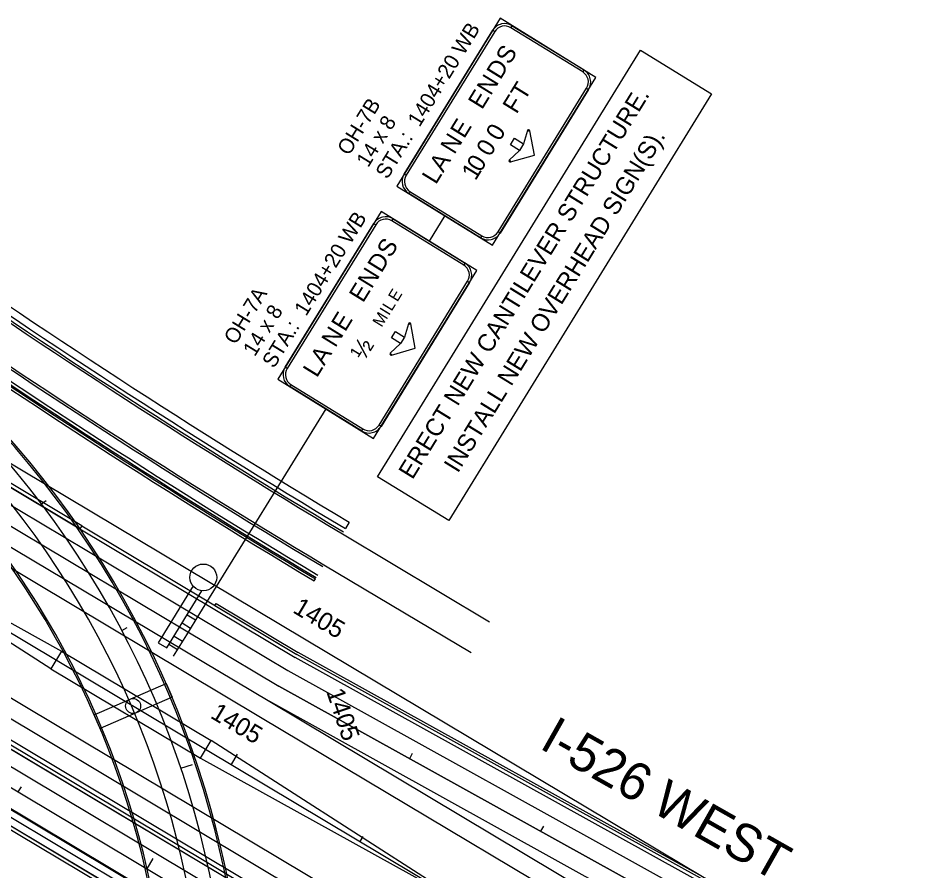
# Model space of a CAD drawing. Extents: x 2338610 to 2351914, y 366540 to 376484.
# Drawn here: x 2346817 to 2347427, y 369410 to 369978 of the extents above; entities that cross this region are included whole.
import ezdxf

# ---------------------------------------------------------------- set-up
doc = ezdxf.new("R2010")
doc.units = 0
for name, color, linetype in [('RD_HC_Cl', 7, 'Continuous'), ('RD_HC_CL_Rel', 7, 'Continuous'), ('RD_PD_Bridge', 7, 'Continuous'), ('RD_PD_Final_LnLine', 7, 'Continuous'), ('RD_PD_Final_TrvlWay', 7, 'Continuous'), ('RD_PD_FOC', 7, 'Continuous'), ('RD_PD_MedBWall', 7, 'Continuous'), ('RD_PD_NOISE-WALL-GM', 7, 'Continuous'), ('RD_PD_PaveShd', 7, 'Continuous'), ('RD_PD_SW', 7, 'Continuous'), ('TR PM UNASSIGNED 3', 7, 'Continuous'), ('TR SN EXTRUDED PANEL SIGNS- MOUNTED OVERHEAD', 7, 'Continuous'), ('TR SN UNASSIGNED 4', 7, 'Continuous'), ('TR SN UNASSIGNED 7', 7, 'Continuous')]:
    doc.layers.add(name, color=color, linetype=linetype)

msp = doc.modelspace()

# ---------------------------------------------------------------- linework, layer by layer
at = {"layer": 'RD_HC_Cl'}
for p, q in [((2346281.57, 369885.43), (2351112.4, 367003.22)), ((2346606.48, 369804.53), (2348463.13, 368696.8)), ((2346606.48, 369804.53), (2348463.13, 368696.8)), ((2346606.48, 369804.53), (2348463.13, 368696.8)), ((2346606.48, 369804.53), (2348463.13, 368696.8))]:
    msp.add_line(p, q, dxfattribs=at)
msp.add_arc((2346341.62, 369282.71), 616, 339.59346, 61.72492, dxfattribs=at)
at = {"layer": 'RD_HC_CL_Rel'}
for p, q in [((2346236.27, 369809.5), (2347935.64, 368795.61)), ((2346990.8, 369533.51), (2347672.36, 369155.93))]:
    msp.add_line(p, q, dxfattribs=at)
at = {"layer": 'RD_PD_Bridge'}
for p, q in [((2346858.25, 369638.21), (2346664.27, 369753.94)), ((2346859.45, 369640.21), (2346665.47, 369755.95)), ((2346859.45, 369640.21), (2346858.25, 369638.21)), ((2346845.89, 369556.79), (2346838.81, 369544.91)), ((2346845.89, 369556.79), (2346945.7, 369497.24)), ((2346838.81, 369544.91), (2346938.61, 369485.37)), ((2346922.55, 369515.94), (2346922.54, 369515.94)), ((2346938.61, 369485.37), (2346945.7, 369497.24))]:
    msp.add_line(p, q, dxfattribs=at)
msp.add_lwpolyline([(2346915.7, 369535.21), (2346919.65, 369526.02), (2346871.71, 369505.22), (2346867.76, 369514.41)], close=True, dxfattribs=at)
msp.add_circle((2346893.7, 369520.21), 5, dxfattribs=at)
for radius, end in [(626, 61.72492), (627.13, 61.72492), (574.88, 58.03805), (576, 58.03805)]:
    msp.add_arc((2346341.62, 369282.71), radius, 339.59346, end, dxfattribs=at)
at = {"layer": 'RD_PD_Final_LnLine'}
for p, q in [((2346312.91, 369937.96), (2346990.8, 369533.51)), ((2346306.76, 369927.65), (2346984.82, 369523.11)), ((2346300.62, 369917.35), (2346978.67, 369512.8)), ((2346262.53, 369853.51), (2348279.79, 368649.96)), ((2346236.27, 369809.5), (2347935.64, 368795.61)), ((2346236.75, 369794.56), (2347945.19, 368775.26)), ((2346236.75, 369794.56), (2347945.19, 368775.26)), ((2346236.75, 369794.56), (2347945.19, 368775.26)), ((2346236.75, 369794.56), (2347945.19, 368775.26)), ((2347033.18, 369634.96), (2347131.36, 369576.38)), ((2347020.88, 369614.35), (2347119.06, 369555.77)), ((2347672.36, 369155.93), (2346990.8, 369533.51)), ((2346978.67, 369512.8), (2348317.92, 368713.76))]:
    msp.add_line(p, q, dxfattribs=at)
for centre, radius, start, end in [((2349486.38, 373746.74), 4788, 234.83658, 239.17851), ((2346341.62, 369282.71), 616, 339.59346, 61.72492), ((2349486.38, 373746.74), 4812, 234.83658, 239.17851)]:
    msp.add_arc(centre, radius, start, end, dxfattribs=at)
at = {"layer": 'RD_PD_Final_TrvlWay'}
for p, q in [((2346319.06, 369948.26), (2346996.78, 369543.91)), ((2346256.38, 369843.21), (2348273.55, 368639.71)), ((2346242.42, 369819.8), (2347941.79, 368805.92)), ((2346217.64, 369806.64), (2347929.49, 368785.3)), ((2346996.78, 369543.91), (2347678.17, 369166.43)), ((2346984.82, 369523.11), (2348324.07, 368724.07)), ((2347389.99, 369298.64), (2346984.82, 369523.11))]:
    msp.add_line(p, q, dxfattribs=at)
msp.add_arc((2346341.62, 369282.71), 600, 339.59346, 61.72492, dxfattribs=at)
at = {"layer": 'RD_PD_FOC'}
for radius in [4786.5, 4813.5]:
    msp.add_arc((2349486.38, 373746.74), radius, 234.83658, 239.17851, dxfattribs=at)
at = {"layer": 'RD_PD_MedBWall'}
for p, q in [((2346321.67, 369738.76), (2347066.1, 369294.6)), ((2346337.76, 369720.62), (2346872.08, 369401.82)), ((2346339.16, 369722.49), (2346873.27, 369403.83)), ((2346692.66, 369641.52), (2346845.89, 369556.79)), ((2346838.81, 369544.91), (2346691.47, 369639.51)), ((2346858.25, 369638.21), (2347001.77, 369552.58)), ((2346859.45, 369640.21), (2347002.93, 369554.61)), ((2347683.02, 369175.17), (2347001.77, 369552.58)), ((2347684.15, 369177.21), (2347002.93, 369554.61)), ((2346753.42, 369526.57), (2347946.91, 368814.5)), ((2346754.62, 369528.57), (2347948.1, 368816.51)), ((2347093.04, 369402.64), (2346945.7, 369497.24)), ((2346938.61, 369485.37), (2347091.84, 369400.64))]:
    msp.add_line(p, q, dxfattribs=at)
for radius in [4820, 4822]:
    msp.add_arc((2349486.38, 373746.74), radius, 234.83658, 239.17851, dxfattribs=at)
at = {"layer": 'RD_PD_NOISE-WALL-GM'}
for p, q in [((2347014.48, 369603.61), (2347015.25, 369604.9)), ((2346948.2, 369587.26), (2347002.93, 369554.61)), ((2346948.22, 369587.25), (2346948.96, 369588.55)), ((2346948.96, 369588.55), (2347003.7, 369555.89)), ((2347684.88, 369178.53), (2347003.66, 369555.92)), ((2347684.15, 369177.21), (2347002.93, 369554.61))]:
    msp.add_line(p, q, dxfattribs=at)
for radius in [4824.5, 4823]:
    msp.add_arc((2349486.38, 373746.74), radius, 234.83658, 239.17851, dxfattribs=at)
at = {"layer": 'RD_PD_PaveShd'}
for p, q in [((2346250.23, 369832.9), (2347949.6, 368819.01)), ((2346250.23, 369832.9), (2348267.49, 368629.35)), ((2346247.54, 369828.39), (2347946.91, 368814.5)), ((2346574.12, 369807.73), (2346858.25, 369638.21)), ((2346319.1, 369734.46), (2347063.54, 369290.31)), ((2346858.25, 369638.21), (2347001.77, 369552.58)), ((2347683.02, 369175.17), (2347001.77, 369552.58))]:
    msp.add_line(p, q, dxfattribs=at)
at = {"layer": 'RD_PD_SW'}
msp.add_line((2347037.79, 369642.69), (2347035.23, 369638.39), dxfattribs=at)
for radius in [4784, 4779]:
    msp.add_arc((2349486.38, 373746.74), radius, 234.83658, 239.17851, dxfattribs=at)
at = {"layer": 'TR SN EXTRUDED PANEL SIGNS- MOUNTED OVERHEAD'}
for p, q in [((2347133.44, 369970.45), (2347134.77, 369969.63)), ((2347145.52, 369972.18), (2347146.34, 369973.51)), ((2347194.25, 369943.98), (2347193.43, 369942.65)), ((2347195.99, 369931.9), (2347197.32, 369931.08)), ((2347156.56, 369903.63), (2347157.31, 369903.4)), ((2347157.31, 369903.4), (2347158.07, 369903.55)), ((2347145, 369883.43), (2347144.46, 369884)), ((2347145.21, 369882.68), (2347145, 369883.43)), ((2347075.71, 369873.8), (2347074.38, 369874.62)), ((2347077.44, 369861.72), (2347078.26, 369863.05)), ((2347054.11, 369841.73), (2347055.44, 369840.91)), ((2347066.2, 369843.47), (2347067.02, 369844.8)), ((2347101.4, 369846.95), (2347090.97, 369830.03)), ((2347138.26, 369835.25), (2347136.93, 369836.07)), ((2347126.18, 369833.52), (2347125.36, 369832.19)), ((2347114.93, 369815.27), (2347114.11, 369813.94)), ((2347116.66, 369803.18), (2347117.99, 369802.36)), ((2347077.23, 369774.92), (2347077.98, 369774.69)), ((2347077.98, 369774.69), (2347078.75, 369774.84)), ((2347065.68, 369754.72), (2347065.13, 369755.29)), ((2347065.88, 369753.97), (2347065.68, 369754.72)), ((2346996.38, 369745.09), (2346995.05, 369745.91)), ((2346998.12, 369733), (2346998.94, 369734.33)), ((2347022.07, 369718.24), (2346938.01, 369581.84)), ((2347046.85, 369704.81), (2347046.03, 369703.48)), ((2347058.94, 369706.54), (2347057.61, 369707.36)), ((2346938.01, 369581.84), (2346929.25, 369567.63)), ((2346929.74, 369581.02), (2346935.39, 369577.54)), ((2346926.36, 369575.55), (2346932.04, 369572.05)), ((2346929.25, 369567.63), (2346920.49, 369553.42)), ((2346917.61, 369561.34), (2346923.28, 369557.84)), ((2346920.98, 369566.81), (2346926.63, 369563.32))]:
    msp.add_line(p, q, dxfattribs=at)
for points in [[(2347133.34, 369827.27), (2347202.24, 369939.06), (2347138.36, 369978.43), (2347069.46, 369866.64), (2347133.34, 369827.27), (2347133.34, 369827.27)], [(2347134.77, 369969.63), (2347075.71, 369873.8), (2347074.38, 369874.62), (2347133.44, 369970.45), (2347134.77, 369969.63), (2347134.77, 369969.63)], [(2347193.43, 369942.65), (2347145.52, 369972.18), (2347146.34, 369973.51), (2347194.25, 369943.98), (2347193.43, 369942.65), (2347193.43, 369942.65)], [(2347056.68, 369672.91), (2347231.93, 369957.26), (2347279.31, 369928.06), (2347104.07, 369643.7)], [(2347136.93, 369836.07), (2347195.99, 369931.9), (2347197.32, 369931.08), (2347138.26, 369835.25), (2347136.93, 369836.07), (2347136.93, 369836.07)], [(2347161.14, 369887.26), (2347158.07, 369903.55), (2347157.31, 369903.4), (2347156.56, 369903.63), (2347153.82, 369894.76), (2347151.15, 369890.43), (2347144.46, 369884), (2347145, 369883.43), (2347145.21, 369882.68), (2347161.14, 369887.26), (2347161.14, 369887.26)], [(2347145.16, 369894.12), (2347147.83, 369898.45), (2347153.82, 369894.76), (2347151.15, 369890.43), (2347145.16, 369894.12), (2347145.16, 369894.12)], [(2347078.26, 369863.05), (2347126.18, 369833.52), (2347125.36, 369832.19), (2347077.44, 369861.72), (2347078.26, 369863.05), (2347078.26, 369863.05)], [(2347054.01, 369698.55), (2347122.91, 369810.35), (2347059.03, 369849.72), (2346990.13, 369737.93), (2347054.01, 369698.55), (2347054.01, 369698.55)], [(2347055.44, 369840.91), (2346996.38, 369745.09), (2346995.05, 369745.91), (2347054.11, 369841.73), (2347055.44, 369840.91), (2347055.44, 369840.91)], [(2347114.11, 369813.94), (2347066.2, 369843.47), (2347067.02, 369844.8), (2347114.93, 369815.27), (2347114.11, 369813.94), (2347114.11, 369813.94)], [(2347057.61, 369707.36), (2347116.66, 369803.18), (2347117.99, 369802.36), (2347058.94, 369706.54), (2347057.61, 369707.36), (2347057.61, 369707.36)], [(2347081.81, 369758.55), (2347078.75, 369774.84), (2347077.98, 369774.69), (2347077.23, 369774.92), (2347074.49, 369766.05), (2347071.83, 369761.72), (2347065.13, 369755.29), (2347065.68, 369754.72), (2347065.88, 369753.97), (2347081.81, 369758.55), (2347081.81, 369758.55)], [(2347065.84, 369765.41), (2347068.5, 369769.74), (2347074.49, 369766.05), (2347071.83, 369761.72), (2347065.84, 369765.41), (2347065.84, 369765.41)], [(2346998.94, 369734.33), (2347046.85, 369704.81), (2347046.03, 369703.48), (2346998.12, 369733), (2346998.94, 369734.33), (2346998.94, 369734.33)]]:
    msp.add_lwpolyline(points, close=True, dxfattribs=at)
msp.add_lwpolyline([(2346933.67, 369600.17), (2346910.37, 369562.37), (2346916.07, 369558.85), (2346939.61, 369597.04)], dxfattribs=at)
msp.add_circle((2346940.49, 369605.9), 8.91, dxfattribs=at)
for centre, radius, start, end in [((2347141.42, 369965.52), 9.38, 58.35428, 148.35449), ((2347141.42, 369965.52), 7.82, 58.35428, 148.35449), ((2347189.33, 369936), 7.82, 328.35434, 58.35455), ((2347189.33, 369936), 9.38, 328.35434, 58.35455), ((2347157.31, 369903.4), 0.782, 11.37946, 162.8271), ((2347145, 369883.43), 0.782, 133.88158, 285.32922), ((2347082.36, 369869.7), 9.38, 148.35449, 238.35413), ((2347082.36, 369869.7), 7.82, 148.35449, 238.35413), ((2347062.1, 369836.81), 9.38, 58.35428, 148.35449), ((2347062.1, 369836.81), 7.82, 58.35428, 148.35449), ((2347130.28, 369840.17), 7.82, 238.35413, 328.35434), ((2347130.28, 369840.17), 9.38, 238.35413, 328.35434), ((2347110.01, 369807.28), 7.82, 328.35434, 58.35455), ((2347110.01, 369807.28), 9.38, 328.35434, 58.35455), ((2347077.98, 369774.69), 0.782, 11.37946, 162.8271), ((2347065.68, 369754.72), 0.782, 133.88158, 285.32922), ((2347003.04, 369740.99), 9.38, 148.35449, 238.35413), ((2347003.04, 369740.99), 7.82, 148.35449, 238.35413), ((2347050.95, 369711.46), 9.38, 238.35413, 328.35434), ((2347050.95, 369711.46), 7.82, 238.35413, 328.35434)]:
    msp.add_arc(centre, radius, start, end, dxfattribs=at)
at = {"layer": 'TR SN UNASSIGNED 7'}
for p, q in [((2346832.54, 369654.8), (2346835.73, 369657.22)), ((2346886.23, 369570.57), (2346889.77, 369572.44)), ((2347078.08, 369485.16), (2347080.02, 369488.66)), ((2346959.21, 369481.13), (2346963.3, 369488)), ((2346925.59, 369478.76), (2346933.18, 369481.31)), ((2346817.18, 369462.91), (2346819.23, 369466.35)), ((2347165.55, 369436.7), (2347167.49, 369440.2)), ((2347045.08, 369429.9), (2347047.13, 369433.33)), ((2346903.06, 369411.67), (2346907.16, 369418.54))]:
    msp.add_line(p, q, dxfattribs=at)

# ---------------------------------------------------------------- texts
at = {"layer": 'TR PM UNASSIGNED 3'}
for s, p in [('STA.:  1404+20 WB', (2347063.16, 369870.67)), ('OH-7B', (2347037.62, 369886.41)), ('14 x 8', (2347050.39, 369878.54)), ('STA.:  1404+20 WB', (2346987.58, 369744.67)), ('OH-7A', (2346962.04, 369760.41)), ('14 x 8', (2346974.81, 369752.54))]:
    msp.add_text(s, height=10, rotation=58.35428, dxfattribs=at).set_placement(p)
at = {"layer": 'TR SN EXTRUDED PANEL SIGNS- MOUNTED OVERHEAD'}
for s, height, rotation, p in [('S', 11.73, 58.35428, (2347144.68, 369946.98)), ('D', 11.73, 58.35428, (2347138.52, 369936.97)), ('N', 11.73, 58.35428, (2347132.03, 369926.44)), ('T', 11.73, 58.35428, (2347154.62, 369922.88)), ('ERECT NEW CANTILEVER STRUCTURE.', 11.7187, 58.35436, (2347079.89, 369670.53)), ('E', 11.73, 58.35428, (2347126.24, 369917.06)), ('F', 11.73, 58.35428, (2347149.26, 369914.18)), ('E', 11.73, 58.35428, (2347114.34, 369897.75)), ('0', 11.73, 58.35428, (2347138.01, 369895.93)), ('N', 11.73, 58.35428, (2347107.85, 369887.22)), ('INSTALL NEW OVERHEAD SIGN(S).', 11.7187, 58.35436, (2347110.11, 369674.88)), ('0', 11.73, 58.35428, (2347131.65, 369885.61)), ('A', 11.73, 58.35428, (2347100.43, 369875.18)), ('0', 11.73, 58.35428, (2347125.29, 369875.28)), ('1', 11.73, 58.35428, (2347121.88, 369869.75)), ('L', 11.73, 58.35428, (2347095.49, 369867.16)), ('S', 11.73, 58.35428, (2347065.36, 369818.27)), ('D', 11.73, 58.35428, (2347059.19, 369808.26)), ('N', 11.73, 58.35428, (2347052.7, 369797.73)), ('E', 11.73, 58.35428, (2347046.92, 369788.35)), ('E', 7.82, 58.35428, (2347069.84, 369789.05)), ('L', 7.82, 58.35428, (2347065.99, 369782.79)), ('E', 11.73, 58.35428, (2347035.02, 369769.04)), ('M', 7.82, 58.35428, (2347059.39, 369772.08)), ('I', 7.82, 58.35428, (2347064.22, 369779.93)), ('N', 11.73, 58.35428, (2347028.53, 369758.51)), ('½', 11.73, 58.35428, (2347047.84, 369749.63)), ('A', 11.73, 58.35428, (2347021.11, 369746.47)), ('L', 11.73, 58.35428, (2347016.17, 369738.45))]:
    msp.add_text(s, height=height, rotation=rotation, dxfattribs=at).set_placement(p)
at = {"layer": 'TR SN UNASSIGNED 4'}
msp.add_text('I-526 WEST', height=25, rotation=330.50912, dxfattribs=at).set_placement((2347163.78, 369492.43))
at = {"layer": 'TR SN UNASSIGNED 7'}
for rotation, p in [(329.17851, (2346999.48, 369582.87)), (288.55797, (2347022.4, 369529.76)), (329.17851, (2346944.55, 369512.68))]:
    msp.add_text('1405', height=12, rotation=rotation, dxfattribs=at).set_placement(p)

doc.saveas('drawing.dxf')
